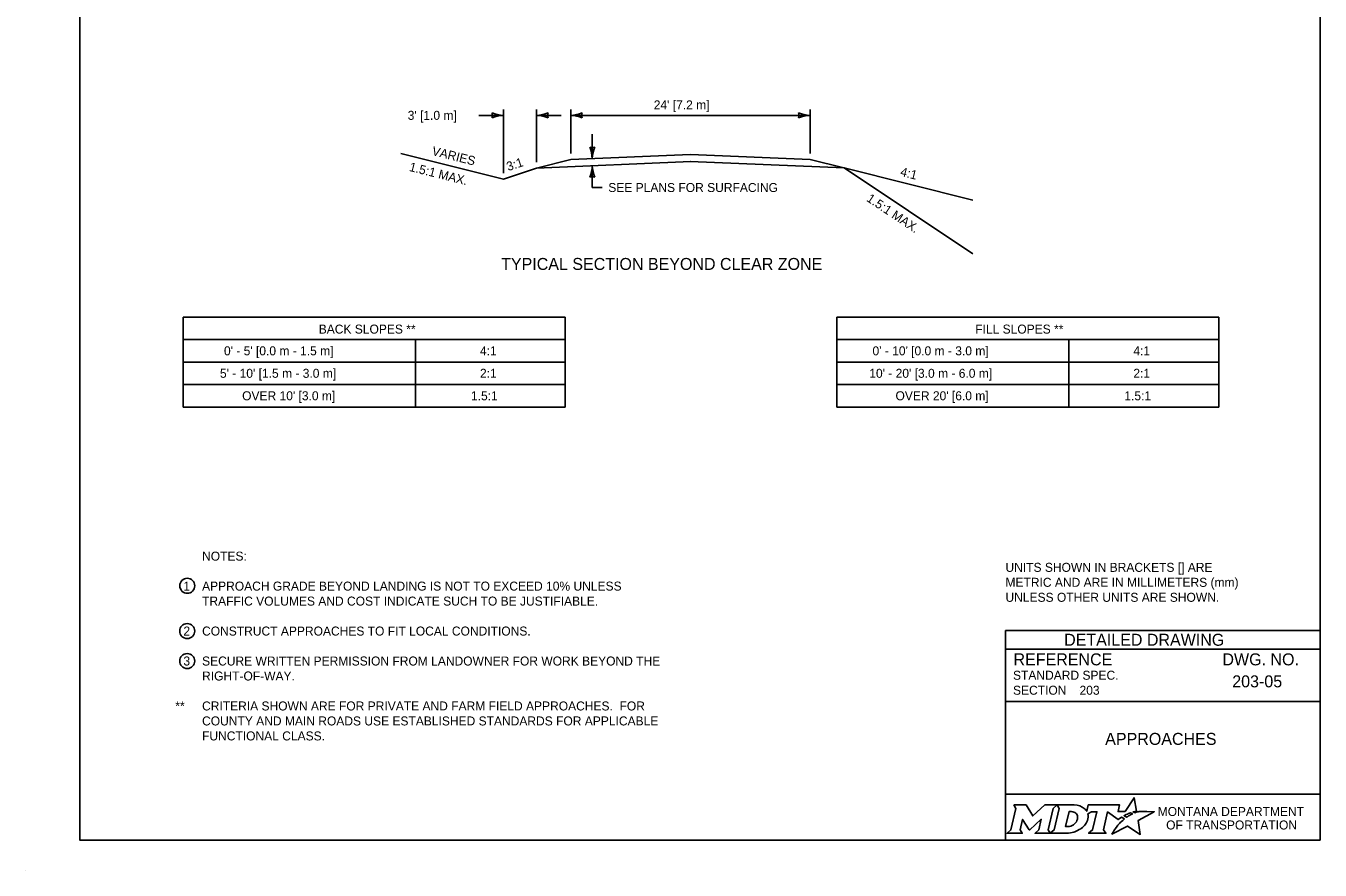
# Model space of a CAD drawing. Extents: x 49991.4 to 50021, y 49987.6 to 50011.4.
# Drawn here: x 49999.98 to 50008.61, y 49999.86 to 50005.5 of the extents above; entities that cross this region are included whole.
import ezdxf

# ---------------------------------------------------------------- set-up
doc = ezdxf.new("R2010")
doc.units = 0
for name, color, linetype in [('Level 1', 7, 'Continuous'), ('Level 2', 7, 'Continuous'), ('Level 3', 7, 'Continuous'), ('Level 4', 7, 'Continuous')]:
    doc.layers.add(name, color=color, linetype=linetype)

msp = doc.modelspace()

# ---------------------------------------------------------------- linework, layer by layer
at = {"layer": 'Level 1'}
for p, q in [((50003.1637, 50004.4744), (50002.4793, 50004.6456)), ((50003.3855, 50004.5483), (50003.6131, 50004.6052)), ((50003.6131, 50004.6052), (50004.4117, 50004.6385)), ((50005.2103, 50004.6052), (50004.4117, 50004.6385)), ((50005.4367, 50004.5486), (50005.2103, 50004.6052)), ((50003.3854, 50004.5483), (50003.1637, 50004.4744)), ((50003.3854, 50004.5483), (50004.4137, 50004.5912)), ((50005.4369, 50004.5486), (50004.4097, 50004.5914)), ((50006.2957, 50004.3339), (50005.4369, 50004.5486)), ((49999.9766, 49999.8624), (49999.9766, 49999.8624))]:
    msp.add_line(p, q, dxfattribs=at)
msp.add_lwpolyline([(50008.6146, 50011.2628), (50000.3356, 50011.2628), (50000.3356, 50000.0624), (50008.6146, 50000.0624)], close=True, dxfattribs=at)
at = {"layer": 'Level 2'}
for p, q in [((50001.0274, 50003.5533), (50003.577, 50003.5533)), ((50001.0274, 50003.5533), (50001.0274, 50002.9533)), ((50003.577, 50003.5533), (50003.577, 50002.9533)), ((50005.3881, 50003.5533), (50007.9377, 50003.5533)), ((50005.3881, 50002.9533), (50005.3881, 50003.5533)), ((50007.9377, 50003.5533), (50007.9377, 50002.9533)), ((50001.0274, 50003.4033), (50003.577, 50003.4033)), ((50002.577, 50003.4033), (50002.577, 50002.9533)), ((50005.3881, 50003.4033), (50007.9377, 50003.4033)), ((50006.9377, 50003.4033), (50006.9377, 50002.9533)), ((50001.0274, 50003.2533), (50003.577, 50003.2533)), ((50005.3881, 50003.2533), (50007.9377, 50003.2533)), ((50001.0274, 50003.1033), (50003.577, 50003.1033)), ((50005.3881, 50003.1033), (50007.9377, 50003.1033)), ((50001.0274, 50002.9533), (50003.577, 50002.9533)), ((50005.3881, 50002.9533), (50007.9377, 50002.9533)), ((50005.9377, 50002.9533), (50007.9377, 50002.9533)), ((50008.6146, 50001.4624), (50006.5146, 50001.4624)), ((50006.5146, 50001.4624), (50006.5146, 50000.0624)), ((50008.6146, 50001.3374), (50006.5146, 50001.3374)), ((50008.2507, 50001.1223), (50008.2507, 50001.1223)), ((50008.6146, 50000.9874), (50006.5146, 50000.9874)), ((50007.0089, 50001.0629), (50007.0089, 50001.0629)), ((50007.5646, 50000.7383), (50007.5646, 50000.7383)), ((50008.6146, 50000.3693), (50006.5146, 50000.3693))]:
    msp.add_line(p, q, dxfattribs=at)
for points in [[(50006.5701, 50000.2974), (50006.5842, 50000.274), (50006.5507, 50000.1307), (50006.525, 50000.1082), (50006.6266, 50000.1082), (50006.6131, 50000.131), (50006.6293, 50000.2011), (50006.673, 50000.1321), (50006.6783, 50000.1321), (50006.7534, 50000.2016), (50006.737, 50000.1305), (50006.7123, 50000.1085), (50006.8139, 50000.1085), (50006.8001, 50000.1318), (50006.8333, 50000.2742)], [(50006.8333, 50000.2742), (50006.8586, 50000.2974), (50006.7762, 50000.2974), (50006.6966, 50000.2244), (50006.6521, 50000.2971), (50006.5701, 50000.2974)], [(50006.9722, 50000.2974), (50006.8586, 50000.2974), (50006.8733, 50000.2745), (50006.8394, 50000.1307), (50006.8139, 50000.1085), (50006.9245, 50000.1085)], [(50007.3771, 50000.2447), (50007.3668, 50000.2503), (50007.3784, 50000.2531), (50007.39, 50000.2551), (50007.3726, 50000.3452), (50007.3131, 50000.2539), (50007.2658, 50000.2532), (50007.2761, 50000.2973), (50007.0669, 50000.2974), (50007.0568, 50000.2549), (50007.051, 50000.2632)], [(50006.9962, 50000.2107), (50006.995, 50000.2026), (50006.9918, 50000.1933), (50006.9876, 50000.1851), (50006.982, 50000.1776), (50006.9755, 50000.1707), (50006.9676, 50000.1644), (50006.9593, 50000.1597), (50006.9502, 50000.1558), (50006.9411, 50000.1535), (50006.9319, 50000.1526), (50006.916, 50000.1526), (50006.9396, 50000.2526), (50006.9556, 50000.2526), (50006.9632, 50000.252), (50006.9708, 50000.2501), (50006.9774, 50000.2471), (50006.9835, 50000.2429), (50006.9883, 50000.2379), (50006.992, 50000.2319), (50006.9947, 50000.2257), (50006.9963, 50000.2183), (50006.9963, 50000.2153), (50006.9962, 50000.2107)], [(50007.0636, 50000.2383), (50007.0882, 50000.2514), (50007.1251, 50000.2514), (50007.0965, 50000.1309), (50007.069, 50000.1082), (50007.1852, 50000.1082), (50007.1682, 50000.1311), (50007.1964, 50000.2513), (50007.2677, 50000.1996), (50007.2888, 50000.2147), (50007.3085, 50000.2038)], [(50007.2527, 50000.1479), (50007.2374, 50000.1235), (50007.2327, 50000.116), (50007.2269, 50000.1074), (50007.2246, 50000.1031), (50007.3299, 50000.1562), (50007.4138, 50000.1011), (50007.4007, 50000.1938), (50007.5076, 50000.2522), (50007.4583, 50000.253), (50007.4282, 50000.2534), (50007.4074, 50000.2537), (50007.4006, 50000.2522), (50007.3957, 50000.251), (50007.3873, 50000.2487), (50007.3771, 50000.2447)], [(50007.3267, 50000.2171), (50007.3243, 50000.2154), (50007.306, 50000.225), (50007.3163, 50000.2307), (50007.3204, 50000.2329), (50007.329, 50000.2369), (50007.3347, 50000.2395), (50007.3426, 50000.2425), (50007.3499, 50000.2452), (50007.3617, 50000.2378), (50007.3577, 50000.2357), (50007.3531, 50000.2332), (50007.3489, 50000.231), (50007.3439, 50000.2281), (50007.342, 50000.227), (50007.3393, 50000.2254), (50007.3368, 50000.224), (50007.3345, 50000.2224), (50007.3319, 50000.2206), (50007.3292, 50000.2188), (50007.3267, 50000.2171)], [(50006.9702, 50000.1158), (50006.9786, 50000.1184), (50006.9916, 50000.1238), (50007.012, 50000.1348)], [(50007.2666, 50000.164), (50007.2666, 50000.164)]]:
    msp.add_lwpolyline(points, dxfattribs=at)
for centre in [(50001.0537, 50001.76), (50001.0531, 50001.458), (50001.0531, 50001.258)]:
    msp.add_circle(centre, 0.05, dxfattribs=at)
for centre, radius, start, end in [((50006.9953, 50000.219), 0.0709, 339.53292, 15.85821), ((50006.9513, 50000.2363), 0.1183, 300.91025, 339.13831)]:
    msp.add_arc(centre, radius, start, end, dxfattribs=at)
for centre, major_axis, ratio, start_param, end_param in [((50006.9701, 50000.25), (0.0834, -0.0037), 0.568097, 0.61298, 1.570796), ((50007.0257, 50000.2573), (0.0361, -0.0295), 0.469099, 1.225588, 1.570796), ((50007.2974, 50000.1941), (-0.0112, -0.0097), 0.021651, 3.157348, 6.283185), ((50006.9248, 50000.2568), (0, 0.1484), 0.987302, 3.139398, 3.456847), ((50007.2597, 50000.1559), (-0.00694, -0.00806), 0.008222, 0, 3.137361), ((50007.2764, 50000.1742), (-0.0098, -0.0102), 0.016458, 3.141593, 6.279097)]:
    msp.add_ellipse(centre, major_axis=major_axis, ratio=ratio, start_param=start_param, end_param=end_param, dxfattribs=at)
at = {"layer": 'Level 3'}
for p, q in [((50003.1637, 50004.9), (50003.0003, 50004.9)), ((50003.1637, 50004.5144), (50003.1637, 50004.94)), ((50003.3855, 50004.5883), (50003.3855, 50004.94)), ((50003.5489, 50004.9), (50003.3855, 50004.9)), ((50003.6131, 50004.6452), (50003.6131, 50004.94)), ((50003.6131, 50004.9), (50005.2103, 50004.9)), ((50005.2103, 50004.6452), (50005.2103, 50004.94)), ((50003.757, 50004.6112), (50003.757, 50004.7746)), ((50003.757, 50004.4182), (50003.757, 50004.5638)), ((50003.757, 50004.4182), (50003.8236, 50004.4182))]:
    msp.add_line(p, q, dxfattribs=at)
for centre, radius, start, end in [((50003.0355, 50004.9), 0.0548, 342.13882, 17.86118), ((50003.1752, 50005.1327), 0.233, 247.92284, 267.17269), ((50003.1729, 50004.6779), 0.2223, 92.36048, 112.54399), ((50003.3763, 50005.1221), 0.2223, 272.36048, 292.54399), ((50003.374, 50004.6673), 0.233, 67.92284, 87.17269), ((50003.5137, 50004.9), 0.0548, 162.13882, 197.86118), ((50003.6016, 50005.1327), 0.233, 272.82731, 292.07716), ((50003.6039, 50004.6779), 0.2223, 67.45601, 87.63952), ((50003.7413, 50004.9), 0.0548, 162.13882, 197.86118), ((50005.2195, 50005.1221), 0.2223, 247.45601, 267.63952), ((50005.0821, 50004.9), 0.0548, 342.13882, 17.86118), ((50005.2218, 50004.6673), 0.233, 92.82731, 112.07716), ((50003.7567, 50004.7396), 0.0548, 252.13882, 287.86118), ((50003.524, 50004.5999), 0.233, 2.82731, 22.07716), ((50003.9789, 50004.6022), 0.2223, 157.45601, 177.63952), ((50003.5349, 50004.573), 0.2223, 337.45601, 357.63952), ((50003.9897, 50004.5753), 0.233, 182.82731, 202.07716), ((50003.757, 50004.4356), 0.0548, 72.13882, 107.86118)]:
    msp.add_arc(centre, radius, start, end, dxfattribs=at)
at = {"layer": 'Level 4'}
msp.add_line((50005.4369, 50004.5486), (50006.2957, 50003.9761), dxfattribs=at)

# ---------------------------------------------------------------- texts
at = {"layer": 'Level 2'}
for s, height, p in [("24' [7.2 m]", 0.06, (50004.1671, 50004.94)), ("3' [1.0 m]", 0.06, (50002.5249, 50004.87)), ('SEE PLANS FOR SURFACING', 0.06, (50003.8636, 50004.3882)), ('TYPICAL SECTION BEYOND CLEAR ZONE', 0.0799, (50003.1487, 50003.8682)), ('BACK SLOPES **', 0.06, (50001.9311, 50003.4433)), ('FILL SLOPES **', 0.06, (50006.3127, 50003.4433)), ("0' - 5' [0.0 m - 1.5 m]", 0.06, (50001.2988, 50003.2983)), ('4:1', 0.06, (50003.0074, 50003.2983)), ("0' - 10' [0.0 m - 3.0 m]", 0.06, (50005.6272, 50003.2983)), ('4:1', 0.06, (50007.3681, 50003.2983)), ("5' - 10' [1.5 m - 3.0 m]", 0.06, (50001.2719, 50003.1483)), ('2:1', 0.06, (50003.0074, 50003.1483)), ("10' - 20' [3.0 m - 6.0 m]", 0.06, (50005.6057, 50003.1483)), ('2:1', 0.06, (50007.3681, 50003.1483)), ("OVER 10' [3.0 m]", 0.06, (50001.4199, 50002.9983)), ('1.5:1', 0.06, (50002.9474, 50002.9983)), ("OVER 20' [6.0 m]", 0.06, (50005.7806, 50002.9983)), ('1.5:1', 0.06, (50007.3081, 50002.9983)), ('NOTES:', 0.06, (50001.1525, 50001.928)), ('UNITS SHOWN IN BRACKETS [] ARE ', 0.06, (50006.5146, 50001.8532)), ('1', 0.06, (50001.0279, 50001.728)), ('APPROACH GRADE BEYOND LANDING IS NOT TO EXCEED 10% UNLESS ', 0.06, (50001.1525, 50001.728)), ('METRIC AND ARE IN MILLIMETERS (mm) ', 0.06, (50006.5146, 50001.7532)), ('TRAFFIC VOLUMES AND COST INDICATE SUCH TO BE JUSTIFIABLE.', 0.06, (50001.1525, 50001.628)), ('UNLESS OTHER UNITS ARE SHOWN.', 0.06, (50006.5146, 50001.6532)), ('2', 0.06, (50001.0279, 50001.428)), ('CONSTRUCT APPROACHES TO FIT LOCAL CONDITIONS.', 0.06, (50001.1525, 50001.428)), ('DETAILED DRAWING', 0.0799, (50006.9063, 50001.3599)), ('3', 0.06, (50001.0279, 50001.228)), ('SECURE WRITTEN PERMISSION FROM LANDOWNER FOR WORK BEYOND THE', 0.06, (50001.1525, 50001.228)), ('REFERENCE', 0.08, (50006.5682, 50001.229)), ('DWG. NO.', 0.08, (50007.9624, 50001.229)), ('RIGHT-OF-WAY.', 0.06, (50001.1525, 50001.128)), ('STANDARD SPEC.', 0.06, (50006.5649, 50001.133)), ('203-05', 0.08, (50008.0281, 50001.0823)), ('SECTION', 0.06, (50006.5649, 50001.033)), ('203', 0.06, (50007.0089, 50001.0329)), ('**', 0.06, (50000.974, 50000.928)), ('CRITERIA SHOWN ARE FOR PRIVATE AND FARM FIELD APPROACHES.  FOR', 0.06, (50001.1525, 50000.928)), ('COUNTY AND MAIN ROADS USE ESTABLISHED STANDARDS FOR APPLICABLE', 0.06, (50001.1525, 50000.828)), ('FUNCTIONAL CLASS.', 0.06, (50001.1525, 50000.728)), ('APPROACHES', 0.08, (50007.18, 50000.6983)), ('MONTANA DEPARTMENT', 0.06, (50007.5308, 50000.2236)), ('OF TRANSPORTATION', 0.06, (50007.587, 50000.1336))]:
    msp.add_text(s, height=height, dxfattribs=at).set_placement(p)
for s, rotation, p in [('VARIES', 345.95588, (50002.6824, 50004.636)), ('3:1', 18.43495, (50003.1959, 50004.5273)), ('1.5:1 MAX.', 345.95588, (50002.5307, 50004.5297)), ('4:1', 345.96376, (50005.8085, 50004.497)), ('1.5:1 MAX.', 326.31147, (50005.5822, 50004.3316))]:
    msp.add_text(s, height=0.06, rotation=rotation, dxfattribs=at).set_placement(p)

doc.saveas('drawing.dxf')
